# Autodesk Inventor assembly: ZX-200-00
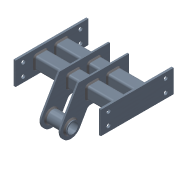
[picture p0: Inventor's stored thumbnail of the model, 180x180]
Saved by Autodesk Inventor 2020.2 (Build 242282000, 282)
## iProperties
Created: 2015-11
Part Number: ZX-200-00
Document SubType Name: Konstrukcja spawana
Designer: F.Stasiak
Weld Material: Stal, miękka
Catalog Web Link: www.expertbooks.pl
Manager: www.cadconsulting.pl
Company: Fabian Stasiak CAD Consulting
Author: F.Stasiak
Subject: Zbiór ćwiczeń. Autodesk Inventor 2020. Kurs Professional
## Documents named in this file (5)
- C:\2020_Kurs_Professional\R4 MES\Zaczep\ZX-200-00.iam
- C:\2020_Kurs_Professional\R4 MES\Zaczep\ZX-200-01.ipt
- C:\2020_Kurs_Professional\R4 MES\Zaczep\ZX-200-02.ipt
- C:\2020_Kurs_Professional\R4 MES\Zaczep\ZX-200-DIN EN 10210-2 - 60 x 60 x 6,3 - 400.ipt
- C:\2020_Kurs_Professional\R4 MES\Zaczep\ZX-200-DIN EN 10220 - 48,3 x 6,3 - 120.ipt
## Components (7 placed, 4 different names)
1. ZX-200-01:1 — Zestawiający:6, Zestawiający:7, Zestawiający:8, Zestawiający:9, Równoległy:3, Równoległy:4, Równoległy:5, Równoległy:6, Zestawiający:11
2. ZX-200-02:1 — Zestawiający:5, Równoległy:2, Zestawiający:11, Zestawiający:13, Równoległy:7
3. ZX-200-DIN EN 10210-2 - 60 x 60 x 6,3 - 400:1 — Równoległy:1, Zestawiający:3, Zestawiający:4, Zestawiający:9, Zestawiający:10
4. ZX-200-DIN EN 10210-2 - 60 x 60 x 6,3 - 400:2 — Równoległy:1, Zestawiający:1, Zestawiający:2, Równoległy:3, Równoległy:4
5. ZX-200-01:2 — Zestawiający:10, Równoległy:5, Równoległy:6, Zestawiający:12
6. ZX-200-02:2 — Zestawiający:1, Zestawiający:2, Zestawiający:3, Zestawiający:4, Zestawiający:5, Równoległy:2, Zestawiający:12
7. ZX-200-DIN EN 10220 - 48,3 x 6,3 - 120:1 — Zestawiający:13, Równoległy:7
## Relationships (20: Mate 13, Flush 7)
- Równoległy:1 [Flush]: ZX-200-DIN EN 10210-2 - 60 x 60 x 6,3 - 400:1 ↔ ZX-200-DIN EN 10210-2 - 60 x 60 x 6,3 - 400:2
- Zestawiający:1 [Mate]: ZX-200-DIN EN 10210-2 - 60 x 60 x 6,3 - 400:2 ↔ ZX-200-02:2
- Zestawiający:2 [Mate]: ZX-200-DIN EN 10210-2 - 60 x 60 x 6,3 - 400:2 ↔ ZX-200-02:2
- Zestawiający:3 [Mate]: ZX-200-DIN EN 10210-2 - 60 x 60 x 6,3 - 400:1 ↔ ZX-200-02:2
- Zestawiający:4 [Mate]: ZX-200-DIN EN 10210-2 - 60 x 60 x 6,3 - 400:1 ↔ ZX-200-02:2
- Zestawiający:5 [Mate]: ZX-200-02:1 ↔ ZX-200-02:2
- Zestawiający:6 [Mate]: ZX-200-01:1
- Zestawiający:7 [Mate]: ZX-200-01:1
- Zestawiający:8 [Mate]: ZX-200-01:1
- Zestawiający:9 [Mate]: ZX-200-01:1 ↔ ZX-200-DIN EN 10210-2 - 60 x 60 x 6,3 - 400:1
- Równoległy:2 [Flush]: ZX-200-02:1 ↔ ZX-200-02:2
- Równoległy:3 [Flush]: ZX-200-01:1 ↔ ZX-200-DIN EN 10210-2 - 60 x 60 x 6,3 - 400:2
- Równoległy:4 [Flush]: ZX-200-01:1 ↔ ZX-200-DIN EN 10210-2 - 60 x 60 x 6,3 - 400:2
- Zestawiający:10 [Mate]: ZX-200-DIN EN 10210-2 - 60 x 60 x 6,3 - 400:1 ↔ ZX-200-01:2
- Równoległy:5 [Flush]: ZX-200-01:1 ↔ ZX-200-01:2
- Równoległy:6 [Flush]: ZX-200-01:1 ↔ ZX-200-01:2
- Zestawiający:11 [Mate]: ZX-200-01:1 ↔ ZX-200-02:1
- Zestawiający:12 [Mate]: ZX-200-01:2 ↔ ZX-200-02:2
- Zestawiający:13 [Mate]: ZX-200-02:1 ↔ ZX-200-DIN EN 10220 - 48,3 x 6,3 - 120:1
- Równoległy:7 [Flush]: ZX-200-02:1 ↔ ZX-200-DIN EN 10220 - 48,3 x 6,3 - 120:1
